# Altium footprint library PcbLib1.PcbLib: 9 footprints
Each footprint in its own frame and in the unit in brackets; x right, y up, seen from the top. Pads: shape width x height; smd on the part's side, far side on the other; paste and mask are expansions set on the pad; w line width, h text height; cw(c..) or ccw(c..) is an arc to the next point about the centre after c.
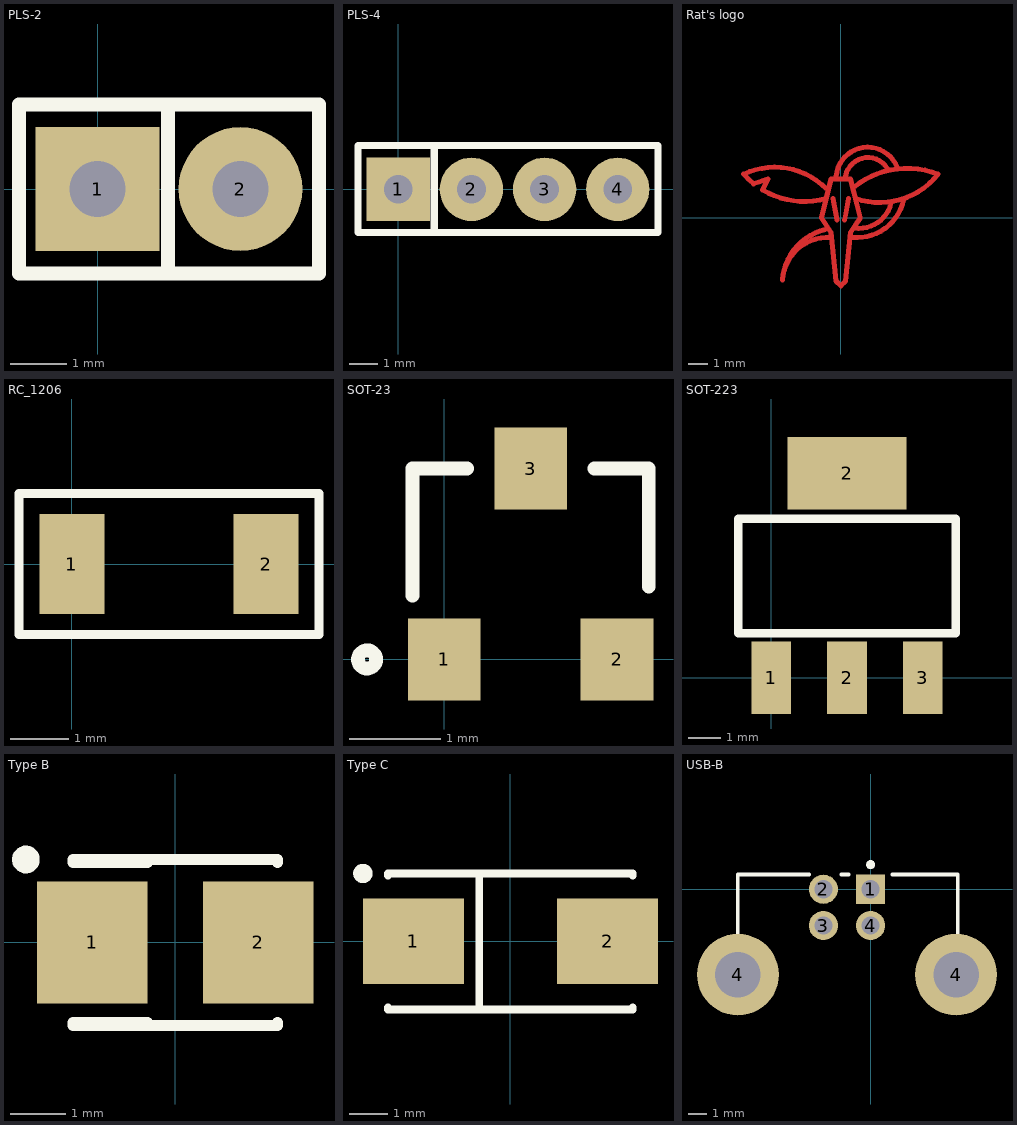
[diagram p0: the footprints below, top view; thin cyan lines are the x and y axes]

## PLS-2 [mm]
height 5
pads (2):
  rect 2.2x2.2 hole 1: 1(0,0)
  round 2.2 hole 1: 2(2.54,0)
Top Overlay:
  lines w0.25: 1.25,-1.5 1.25,1.5 ; -1.397,-1.5 3.937,-1.5 3.937,1.5 -1.397,1.5 -1.397,-1.5
3D body: height 8.54, standoff -3, extent -1.27,-1.27 3.81,1.27

## PLS-4 [mm]
height 5
pads (4):
  rect 2.2x2.2 hole 1: 1(0,0)
  round 2.2 hole 1: 2(2.54,0) 3(5.08,0) 4(7.62,0)
Top Overlay:
  lines w0.25: 1.25,-1.5 1.25,1.5 ; -1.397,-1.5 9.017,-1.5 9.017,1.524 -1.397,1.524 -1.397,-1.5
3D body: height 8.54, standoff -3, extent -1.27,-1.27 8.89,1.27

## Rat's logo [mm]
Top Layer:
  lines w0.254: -4.516,1.786 cw(c-1.875,5.025) -5,2.25 cw(c-3.402,-1.109) -0.75,1.5 ; -4.5,1.75 -3.75,2 -4,1.5 ; -4.033,1.446 ccw(c-1.875,5.025) -0.75,1 ; -0.8,-0.6 ccw(c-0.153,-3.378) -3,-3.2 cw(c-0.65,-3.35) -0.5,-1 ; -0.4,1 -0.2,-0.1 ; -0.238,2.147 cw(c1.384,2.012) 2.9,2.6 ; 0.2,-0.1 0.4,1 ; 0.239,2.148 cw(c1.394,1.929) 2.395,2.546 ; 0.6,-1 ccw(c0.831,1.445) 3.23,0.923 ; 0.652,1.562 cw(c3.411,-1.797) 5,2.25 cw(c2,4.6) 0.75,1 ; 0.711,-0.52 ccw(c0.937,1.169) 2.6,0.8 ; -1,0 -0.5,-0.75 -0.25,-3.25 0,-3.5 0.25,-3.25 0.5,-0.75 1,0 0.5,2 -0.5,2 -1,0

## RC_1206 [mm]
height 1.5
pads (2):
  rect 1.1x1.7 smd: 1(0,0) 2(3.3,0)
Top Overlay:
  lines w0.15: -0.9,-1.2 -0.9,1.2 4.2,1.2 4.2,-1.2 -0.9,-1.2
3D body: height 0.85, standoff 0, extent -0.025,-0.865 3.325,0.865

## SOT-23 [mm]
height 1.2
pads (3):
  rect 0.8x0.9 smd: 1(0,0) 2(1.9,0) 3(0.95,2.1)
Top Overlay:
  circle w0.15: c-0.85,0 r0.1
  lines w0.15: -0.35,0.7 -0.35,2.1 0.25,2.1 ; 1.65,2.1 2.25,2.1 2.25,0.8
3D body: height 1.06, standoff -0.04, extent -0.55,-0.3 2.45,2.2

## SOT-223 [mm]
height 1.5
pads (4):
  rect 1.2x2.2 smd: 1(0,0) 2(2.3,0) 3(4.6,0)
  rect 3.6x2.2 smd: 2(2.3,6.2)
Top Overlay:
  lines w0.254: -1,1.35 5.6,1.35 5.6,4.826 -1,4.826 -1,1.35
3D body: height 1.65, standoff 0, extent -0.95,-0.443 5.55,6.644

## Type B [mm]
height 2.5
pads (2):
  rect 2x2.2 smd: 1(-1.5,0) 2(1.5,0)
Top Overlay:
  circle w0.25: c-2.7,1.5 r0.125
  lines w0.2: -1.85,-1.5 1.85,-1.5 1.85,-1.45 ; -1.85,-1.45 -0.5,-1.45 ; -1.85,1.45 -0.5,1.45 ; -1.85,1.5 1.85,1.5 1.85,1.45
3D body: height 1.89, standoff -0.02, extent -1.831,-1.4 1.832,1.4

## Type C [mm]
height 3.4
pads (2):
  rect 2.6x2.2 smd: 1(-2.5,0) 2(2.5,0)
Top Overlay:
  circle w0.25: c-3.8,1.75 r0.125
  lines w0.2: -3.15,-1.7 -3.15,-1.75 3.15,-1.75 3.15,-1.7 ; -3.15,1.7 -3.15,1.75 3.15,1.75 3.15,1.7 ; -0.8,-1.75 -0.8,1.75
3D body: height 2.79, standoff -0.04, extent -3.799,-1.8 3.799,1.713

## USB-B [mm]
height 10
pads (6):
  rect 1.6x1.6 hole 1: 1(0,0)
  round 1.6 hole 1: 2(-2.6,0) 3(-2.6,-2) 4(0,-2)
  round 4.5 hole 2.5: 4(-7.3,-4.7) 4(4.7,-4.7)
Top Overlay:
  circle w0.25: c0,1.35 r0.125
  lines w0.2: -7.3,-2.41 -7.3,0.81 -3.39,0.81 ; -1.61,0.81 -1.2,0.81 ; 1.2,0.81 4.8,0.81 4.8,-2.41
3D body: height 10.7, standoff -3.8, extent -8.738,-14.831 5.955,1.369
